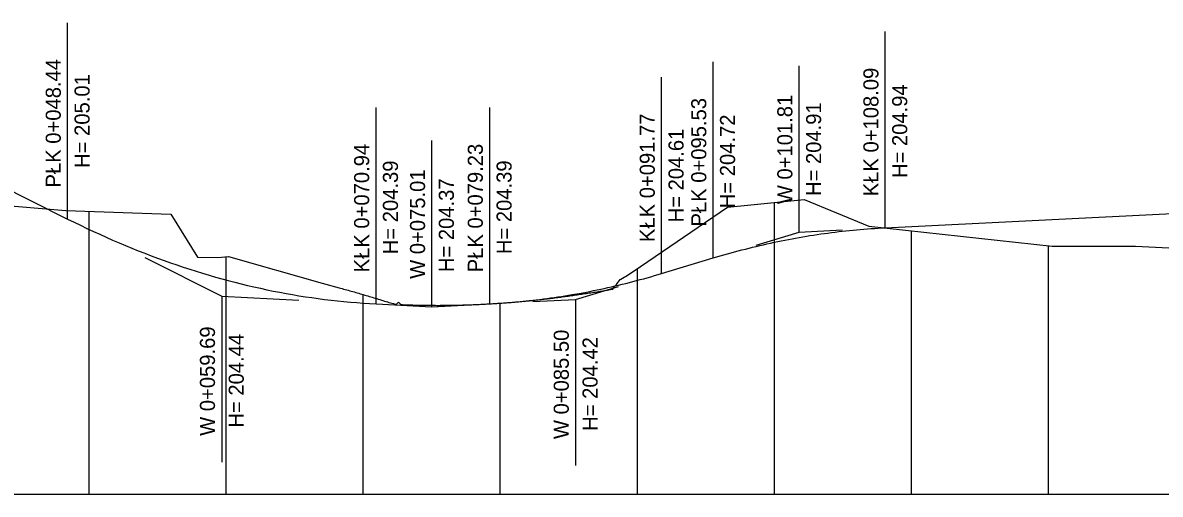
# Model space of a CAD drawing. Extents: x 6512707 to 6513007, y 6022307 to 6022469.
# Drawn here: x 6512789.6 to 6512872.6, y 6022368.6 to 6022402.9 of the extents above; entities that cross this region are included whole.
import ezdxf

# ---------------------------------------------------------------- set-up
doc = ezdxf.new("R2010")
doc.units = 0
doc.layers.add('1', color=7, linetype='Continuous')
doc.layers.add('42', color=7, linetype='Continuous')

msp = doc.modelspace()

# ---------------------------------------------------------------- linework, layer by layer
for p, q in [((6512772.058, 6022399.019), (6512792.862, 6022388.618)), ((6512772.058, 6022399.019), (6512792.862, 6022388.618)), ((6512852.505, 6022387.983), (6512903.729, 6022390.547)), ((6512852.505, 6022387.983), (6512903.729, 6022390.547)), ((6512836.189, 6022384.646), (6512839.946, 6022385.777)), ((6512836.189, 6022384.646), (6512839.946, 6022385.777)), ((6512815.356, 6022382.432), (6512819.433, 6022382.228)), ((6512815.356, 6022382.432), (6512819.433, 6022382.228)), ((6512819.433, 6022382.228), (6512823.647, 6022382.441)), ((6512819.433, 6022382.228), (6512823.647, 6022382.441))]:
    msp.add_line(p, q)
for points in [[(6512792.862, 6022388.618), (6512793.331, 6022388.386), (6512793.799, 6022388.158), (6512794.268, 6022387.935), (6512794.737, 6022387.716), (6512795.205, 6022387.502), (6512795.674, 6022387.291), (6512796.142, 6022387.086), (6512796.611, 6022386.884), (6512797.08, 6022386.687), (6512797.548, 6022386.495), (6512798.017, 6022386.307), (6512798.486, 6022386.123), (6512798.954, 6022385.943), (6512799.423, 6022385.769), (6512799.891, 6022385.598), (6512800.36, 6022385.432), (6512800.829, 6022385.27), (6512801.297, 6022385.112), (6512801.766, 6022384.959), (6512802.235, 6022384.811), (6512802.703, 6022384.667), (6512803.172, 6022384.527), (6512803.64, 6022384.391), (6512804.578, 6022384.134), (6512805.046, 6022384.011), (6512805.515, 6022383.893), (6512805.984, 6022383.78), (6512806.452, 6022383.671), (6512806.921, 6022383.566), (6512807.39, 6022383.466), (6512807.858, 6022383.37), (6512808.327, 6022383.278), (6512808.795, 6022383.191), (6512809.264, 6022383.108), (6512809.733, 6022383.03), (6512810.201, 6022382.956), (6512810.67, 6022382.886), (6512811.139, 6022382.821), (6512811.607, 6022382.76), (6512812.076, 6022382.704), (6512812.544, 6022382.652), (6512813.013, 6022382.604), (6512813.482, 6022382.561), (6512813.95, 6022382.522), (6512814.419, 6022382.488), (6512814.888, 6022382.458), (6512815.356, 6022382.432)], [(6512792.862, 6022388.618), (6512793.331, 6022388.386), (6512793.799, 6022388.158), (6512794.268, 6022387.935), (6512794.737, 6022387.716), (6512795.205, 6022387.502), (6512795.674, 6022387.291), (6512796.142, 6022387.086), (6512796.611, 6022386.884), (6512797.08, 6022386.687), (6512797.548, 6022386.495), (6512798.017, 6022386.307), (6512798.486, 6022386.123), (6512798.954, 6022385.943), (6512799.423, 6022385.769), (6512799.891, 6022385.598), (6512800.36, 6022385.432), (6512800.829, 6022385.27), (6512801.297, 6022385.112), (6512801.766, 6022384.959), (6512802.235, 6022384.811), (6512802.703, 6022384.667), (6512803.172, 6022384.527), (6512803.64, 6022384.391), (6512804.578, 6022384.134), (6512805.046, 6022384.011), (6512805.515, 6022383.893), (6512805.984, 6022383.78), (6512806.452, 6022383.671), (6512806.921, 6022383.566), (6512807.39, 6022383.466), (6512807.858, 6022383.37), (6512808.327, 6022383.278), (6512808.795, 6022383.191), (6512809.264, 6022383.108), (6512809.733, 6022383.03), (6512810.201, 6022382.956), (6512810.67, 6022382.886), (6512811.139, 6022382.821), (6512811.607, 6022382.76), (6512812.076, 6022382.704), (6512812.544, 6022382.652), (6512813.013, 6022382.604), (6512813.482, 6022382.561), (6512813.95, 6022382.522), (6512814.419, 6022382.488), (6512814.888, 6022382.458), (6512815.356, 6022382.432)], [(6512839.946, 6022385.777), (6512840.207, 6022385.855), (6512840.469, 6022385.932), (6512840.731, 6022386.008), (6512840.992, 6022386.082), (6512841.254, 6022386.154), (6512841.516, 6022386.225), (6512841.777, 6022386.295), (6512842.039, 6022386.364), (6512842.301, 6022386.431), (6512842.562, 6022386.497), (6512842.824, 6022386.561), (6512843.086, 6022386.624), (6512843.347, 6022386.686), (6512843.609, 6022386.746), (6512843.871, 6022386.805), (6512844.132, 6022386.863), (6512844.394, 6022386.919), (6512844.656, 6022386.974), (6512844.917, 6022387.028), (6512845.179, 6022387.08), (6512845.44, 6022387.13), (6512845.702, 6022387.18), (6512845.964, 6022387.228), (6512846.487, 6022387.32), (6512846.749, 6022387.364), (6512847.01, 6022387.406), (6512847.272, 6022387.447), (6512847.534, 6022387.487), (6512847.795, 6022387.526), (6512848.057, 6022387.563), (6512848.319, 6022387.598), (6512848.58, 6022387.633), (6512848.842, 6022387.666), (6512849.104, 6022387.697), (6512849.365, 6022387.727), (6512849.627, 6022387.756), (6512849.889, 6022387.784), (6512850.15, 6022387.81), (6512850.412, 6022387.835), (6512850.673, 6022387.858), (6512850.935, 6022387.88), (6512851.197, 6022387.901), (6512851.458, 6022387.92), (6512851.72, 6022387.938), (6512851.982, 6022387.954), (6512852.243, 6022387.969), (6512852.505, 6022387.983)], [(6512839.946, 6022385.777), (6512840.207, 6022385.855), (6512840.469, 6022385.932), (6512840.731, 6022386.008), (6512840.992, 6022386.082), (6512841.254, 6022386.154), (6512841.516, 6022386.225), (6512841.777, 6022386.295), (6512842.039, 6022386.364), (6512842.301, 6022386.431), (6512842.562, 6022386.497), (6512842.824, 6022386.561), (6512843.086, 6022386.624), (6512843.347, 6022386.686), (6512843.609, 6022386.746), (6512843.871, 6022386.805), (6512844.132, 6022386.863), (6512844.394, 6022386.919), (6512844.656, 6022386.974), (6512844.917, 6022387.028), (6512845.179, 6022387.08), (6512845.44, 6022387.13), (6512845.702, 6022387.18), (6512845.964, 6022387.228), (6512846.487, 6022387.32), (6512846.749, 6022387.364), (6512847.01, 6022387.406), (6512847.272, 6022387.447), (6512847.534, 6022387.487), (6512847.795, 6022387.526), (6512848.057, 6022387.563), (6512848.319, 6022387.598), (6512848.58, 6022387.633), (6512848.842, 6022387.666), (6512849.104, 6022387.697), (6512849.365, 6022387.727), (6512849.627, 6022387.756), (6512849.889, 6022387.784), (6512850.15, 6022387.81), (6512850.412, 6022387.835), (6512850.673, 6022387.858), (6512850.935, 6022387.88), (6512851.197, 6022387.901), (6512851.458, 6022387.92), (6512851.72, 6022387.938), (6512851.982, 6022387.954), (6512852.243, 6022387.969), (6512852.505, 6022387.983)], [(6512823.647, 6022382.441), (6512823.908, 6022382.454), (6512824.169, 6022382.47), (6512824.431, 6022382.486), (6512824.692, 6022382.504), (6512824.953, 6022382.523), (6512825.215, 6022382.544), (6512825.476, 6022382.566), (6512825.737, 6022382.59), (6512825.998, 6022382.614), (6512826.26, 6022382.64), (6512826.521, 6022382.668), (6512826.782, 6022382.697), (6512827.044, 6022382.727), (6512827.305, 6022382.759), (6512827.566, 6022382.792), (6512827.827, 6022382.826), (6512828.089, 6022382.862), (6512828.35, 6022382.899), (6512828.611, 6022382.937), (6512828.873, 6022382.977), (6512829.134, 6022383.018), (6512829.395, 6022383.061), (6512829.657, 6022383.105), (6512830.179, 6022383.196), (6512830.44, 6022383.244), (6512830.702, 6022383.294), (6512830.963, 6022383.344), (6512831.224, 6022383.397), (6512831.486, 6022383.45), (6512831.747, 6022383.505), (6512832.008, 6022383.561), (6512832.269, 6022383.618), (6512832.531, 6022383.677), (6512832.792, 6022383.738), (6512833.053, 6022383.799), (6512833.315, 6022383.862), (6512833.576, 6022383.927), (6512833.837, 6022383.992), (6512834.098, 6022384.06), (6512834.36, 6022384.128), (6512834.621, 6022384.198), (6512834.882, 6022384.269), (6512835.144, 6022384.342), (6512835.405, 6022384.416), (6512835.666, 6022384.491), (6512835.927, 6022384.567), (6512836.189, 6022384.646)], [(6512823.647, 6022382.441), (6512823.908, 6022382.454), (6512824.169, 6022382.47), (6512824.431, 6022382.486), (6512824.692, 6022382.504), (6512824.953, 6022382.523), (6512825.215, 6022382.544), (6512825.476, 6022382.566), (6512825.737, 6022382.59), (6512825.998, 6022382.614), (6512826.26, 6022382.64), (6512826.521, 6022382.668), (6512826.782, 6022382.697), (6512827.044, 6022382.727), (6512827.305, 6022382.759), (6512827.566, 6022382.792), (6512827.827, 6022382.826), (6512828.089, 6022382.862), (6512828.35, 6022382.899), (6512828.611, 6022382.937), (6512828.873, 6022382.977), (6512829.134, 6022383.018), (6512829.395, 6022383.061), (6512829.657, 6022383.105), (6512830.179, 6022383.196), (6512830.44, 6022383.244), (6512830.702, 6022383.294), (6512830.963, 6022383.344), (6512831.224, 6022383.397), (6512831.486, 6022383.45), (6512831.747, 6022383.505), (6512832.008, 6022383.561), (6512832.269, 6022383.618), (6512832.531, 6022383.677), (6512832.792, 6022383.738), (6512833.053, 6022383.799), (6512833.315, 6022383.862), (6512833.576, 6022383.927), (6512833.837, 6022383.992), (6512834.098, 6022384.06), (6512834.36, 6022384.128), (6512834.621, 6022384.198), (6512834.882, 6022384.269), (6512835.144, 6022384.342), (6512835.405, 6022384.416), (6512835.666, 6022384.491), (6512835.927, 6022384.567), (6512836.189, 6022384.646)]]:
    msp.add_lwpolyline(points)
at = {"layer": '1'}
for p, q in [((6512844.419, 6022368.562), (6512844.419, 6022389.818)), ((6512794.419, 6022368.562), (6512794.419, 6022389.178)), ((6512846.225, 6022387.669), (6512849.365, 6022387.826)), ((6512854.419, 6022368.562), (6512854.419, 6022387.76)), ((6512843.086, 6022386.723), (6512846.225, 6022387.669)), ((6512864.419, 6022368.562), (6512864.419, 6022386.656)), ((6512798.486, 6022385.807), (6512804.109, 6022382.995)), ((6512804.419, 6022368.562), (6512804.419, 6022385.871)), ((6512834.419, 6022368.562), (6512834.419, 6022385.005)), ((6512829.918, 6022382.757), (6512833.053, 6022383.701)), ((6512804.109, 6022382.995), (6512809.733, 6022382.714)), ((6512814.419, 6022368.562), (6512814.419, 6022383.111)), ((6512826.782, 6022382.599), (6512829.918, 6022382.757)), ((6512824.419, 6022368.562), (6512824.419, 6022382.489)), ((6512844.419, 6022368.562), (6512844.419, 6022370.562)), ((6512794.419, 6022368.562), (6512794.419, 6022369.562)), ((6512804.419, 6022368.562), (6512804.419, 6022369.562)), ((6512814.419, 6022368.562), (6512814.419, 6022369.562)), ((6512824.419, 6022368.562), (6512824.419, 6022369.562)), ((6512834.419, 6022368.562), (6512834.419, 6022369.562)), ((6512854.419, 6022368.562), (6512854.419, 6022369.562)), ((6512864.419, 6022368.562), (6512864.419, 6022369.562)), ((6512744.419, 6022368.562), (6512954.419, 6022368.562))]:
    msp.add_line(p, q, dxfattribs=at)
msp.add_lwpolyline([(6512785.792, 6022389.821), (6512792.74, 6022389.234), (6512800.397, 6022388.979), (6512802.33, 6022385.835), (6512803.827, 6022385.822), (6512804.601, 6022385.885), (6512811.417, 6022383.941), (6512812.664, 6022383.606), (6512812.774, 6022383.577), (6512812.884, 6022383.547), (6512812.994, 6022383.517), (6512813.104, 6022383.487), (6512813.214, 6022383.456), (6512813.324, 6022383.426), (6512813.434, 6022383.395), (6512813.544, 6022383.364), (6512813.654, 6022383.333), (6512813.764, 6022383.302), (6512813.874, 6022383.27), (6512813.984, 6022383.239), (6512814.094, 6022383.207), (6512814.204, 6022383.175), (6512814.314, 6022383.143), (6512814.423, 6022383.111), (6512814.533, 6022383.078), (6512814.643, 6022383.046), (6512814.753, 6022383.013), (6512814.863, 6022382.98), (6512814.973, 6022382.947), (6512815.083, 6022382.913), (6512815.193, 6022382.88), (6512815.303, 6022382.846), (6512815.413, 6022382.813), (6512815.523, 6022382.779), (6512815.633, 6022382.745), (6512815.743, 6022382.71), (6512815.853, 6022382.676), (6512815.963, 6022382.642), (6512816.073, 6022382.607), (6512816.089, 6022382.602), (6512816.183, 6022382.575), (6512816.293, 6022382.544), (6512816.402, 6022382.512), (6512816.512, 6022382.481), (6512816.622, 6022382.449), (6512816.732, 6022382.418), (6512816.764, 6022382.409), (6512816.842, 6022382.401), (6512816.857, 6022382.4), (6512816.952, 6022382.508), (6512816.997, 6022382.559), (6512817.062, 6022382.486), (6512817.154, 6022382.384), (6512817.172, 6022382.383), (6512817.282, 6022382.378), (6512817.392, 6022382.374), (6512817.502, 6022382.37), (6512817.612, 6022382.366), (6512817.722, 6022382.362), (6512817.832, 6022382.359), (6512817.942, 6022382.356), (6512818.052, 6022382.353), (6512818.162, 6022382.35), (6512818.272, 6022382.347), (6512818.381, 6022382.344), (6512818.491, 6022382.342), (6512818.601, 6022382.34), (6512818.711, 6022382.338), (6512818.821, 6022382.336), (6512818.931, 6022382.334), (6512819.041, 6022382.333), (6512819.151, 6022382.331), (6512819.261, 6022382.33), (6512819.371, 6022382.329), (6512819.481, 6022382.329), (6512819.591, 6022382.328), (6512819.701, 6022382.328), (6512819.811, 6022382.327), (6512819.921, 6022382.327), (6512820.031, 6022382.328), (6512820.141, 6022382.328), (6512820.25, 6022382.329), (6512820.36, 6022382.329), (6512820.47, 6022382.33), (6512820.58, 6022382.331), (6512820.69, 6022382.333), (6512820.8, 6022382.334), (6512820.91, 6022382.336), (6512821.02, 6022382.338), (6512821.13, 6022382.34), (6512821.24, 6022382.342), (6512821.35, 6022382.345), (6512821.46, 6022382.347), (6512821.57, 6022382.35), (6512821.68, 6022382.353), (6512821.79, 6022382.356), (6512821.9, 6022382.36), (6512822.01, 6022382.363), (6512822.12, 6022382.367), (6512822.229, 6022382.371), (6512822.339, 6022382.375), (6512822.449, 6022382.379), (6512822.559, 6022382.384), (6512822.669, 6022382.388), (6512822.779, 6022382.393), (6512822.889, 6022382.398), (6512822.999, 6022382.403), (6512823.109, 6022382.409), (6512823.219, 6022382.414), (6512823.329, 6022382.42), (6512823.439, 6022382.426), (6512823.549, 6022382.432), (6512823.659, 6022382.438), (6512823.769, 6022382.445), (6512823.879, 6022382.451), (6512823.989, 6022382.458), (6512824.099, 6022382.465), (6512824.208, 6022382.473), (6512824.318, 6022382.48), (6512824.428, 6022382.487), (6512824.538, 6022382.495), (6512824.648, 6022382.503), (6512824.758, 6022382.511), (6512824.868, 6022382.519), (6512824.978, 6022382.528), (6512825.088, 6022382.536), (6512825.198, 6022382.545), (6512825.308, 6022382.554), (6512825.418, 6022382.563), (6512825.528, 6022382.573), (6512825.638, 6022382.582), (6512825.748, 6022382.592), (6512825.858, 6022382.602), (6512825.968, 6022382.612), (6512826.078, 6022382.622), (6512826.187, 6022382.632), (6512826.297, 6022382.643), (6512826.407, 6022382.653), (6512826.517, 6022382.664), (6512826.627, 6022382.675), (6512826.737, 6022382.686), (6512826.847, 6022382.698), (6512826.957, 6022382.709), (6512827.067, 6022382.721), (6512827.177, 6022382.733), (6512827.287, 6022382.745), (6512827.397, 6022382.757), (6512827.507, 6022382.769), (6512827.617, 6022382.782), (6512827.727, 6022382.794), (6512827.837, 6022382.807), (6512827.947, 6022382.82), (6512828.057, 6022382.833), (6512828.166, 6022382.847), (6512828.276, 6022382.86), (6512828.386, 6022382.874), (6512828.496, 6022382.887), (6512828.606, 6022382.901), (6512828.716, 6022382.915), (6512828.826, 6022382.93), (6512828.936, 6022382.944), (6512829.046, 6022382.959), (6512829.156, 6022382.973), (6512829.266, 6022382.988), (6512829.376, 6022383.003), (6512829.486, 6022383.018), (6512829.596, 6022383.034), (6512829.706, 6022383.049), (6512829.816, 6022383.065), (6512829.926, 6022383.081), (6512830.036, 6022383.096), (6512830.145, 6022383.112), (6512830.255, 6022383.129), (6512830.365, 6022383.145), (6512830.475, 6022383.161), (6512830.585, 6022383.178), (6512830.695, 6022383.195), (6512830.805, 6022383.212), (6512830.915, 6022383.229), (6512831.025, 6022383.246), (6512831.135, 6022383.263), (6512831.245, 6022383.281), (6512831.355, 6022383.298), (6512831.465, 6022383.316), (6512831.575, 6022383.334), (6512831.685, 6022383.352), (6512831.795, 6022383.37), (6512831.905, 6022383.388), (6512832.015, 6022383.406), (6512832.124, 6022383.425), (6512832.234, 6022383.444), (6512832.344, 6022383.462), (6512832.454, 6022383.481), (6512832.564, 6022383.5), (6512832.619, 6022383.51), (6512832.674, 6022383.578), (6512832.784, 6022383.715), (6512832.894, 6022383.854), (6512833.004, 6022383.995), (6512833.114, 6022384.137), (6512833.174, 6022384.215), (6512833.224, 6022384.243), (6512833.334, 6022384.306), (6512833.444, 6022384.371), (6512833.554, 6022384.437), (6512833.664, 6022384.505), (6512833.774, 6022384.574), (6512833.884, 6022384.645), (6512833.994, 6022384.717), (6512834.104, 6022384.791), (6512841.002, 6022389.472), (6512846.593, 6022390.038), (6512851.292, 6022388.105), (6512864.674, 6022386.628), (6512870.758, 6022386.649), (6512880.453, 6022386.148)], dxfattribs=at)
at = {"layer": '42'}
for p, q in [((6512792.862, 6022388.618), (6512792.862, 6022402.918)), ((6512852.505, 6022387.983), (6512852.505, 6022402.283)), ((6512839.946, 6022385.777), (6512839.946, 6022400.077)), ((6512846.225, 6022387.669), (6512846.225, 6022399.769)), ((6512772.058, 6022399.019), (6512792.862, 6022388.618)), ((6512836.189, 6022384.646), (6512836.189, 6022398.946)), ((6512815.356, 6022382.432), (6512815.356, 6022396.732)), ((6512823.647, 6022382.441), (6512823.647, 6022396.741)), ((6512819.433, 6022382.228), (6512819.433, 6022394.328)), ((6512852.505, 6022387.983), (6512903.729, 6022390.547)), ((6512836.189, 6022384.646), (6512839.946, 6022385.777)), ((6512804.109, 6022382.995), (6512804.109, 6022370.895)), ((6512829.918, 6022382.757), (6512829.918, 6022370.657)), ((6512815.356, 6022382.432), (6512819.433, 6022382.228)), ((6512819.433, 6022382.228), (6512823.647, 6022382.441))]:
    msp.add_line(p, q, dxfattribs=at)
for points in [[(6512792.862, 6022388.618), (6512793.331, 6022388.386), (6512793.799, 6022388.158), (6512794.268, 6022387.935), (6512794.737, 6022387.716), (6512795.205, 6022387.502), (6512795.674, 6022387.291), (6512796.142, 6022387.086), (6512796.611, 6022386.884), (6512797.08, 6022386.687), (6512797.548, 6022386.495), (6512798.017, 6022386.307), (6512798.486, 6022386.123), (6512798.954, 6022385.943), (6512799.423, 6022385.769), (6512799.891, 6022385.598), (6512800.36, 6022385.432), (6512800.829, 6022385.27), (6512801.297, 6022385.112), (6512801.766, 6022384.959), (6512802.235, 6022384.811), (6512802.703, 6022384.667), (6512803.172, 6022384.527), (6512803.64, 6022384.391), (6512804.578, 6022384.134), (6512805.046, 6022384.011), (6512805.515, 6022383.893), (6512805.984, 6022383.78), (6512806.452, 6022383.671), (6512806.921, 6022383.566), (6512807.39, 6022383.466), (6512807.858, 6022383.37), (6512808.327, 6022383.278), (6512808.795, 6022383.191), (6512809.264, 6022383.108), (6512809.733, 6022383.03), (6512810.201, 6022382.956), (6512810.67, 6022382.886), (6512811.139, 6022382.821), (6512811.607, 6022382.76), (6512812.076, 6022382.704), (6512812.544, 6022382.652), (6512813.013, 6022382.604), (6512813.482, 6022382.561), (6512813.95, 6022382.522), (6512814.419, 6022382.488), (6512814.888, 6022382.458), (6512815.356, 6022382.432)], [(6512839.946, 6022385.777), (6512840.207, 6022385.855), (6512840.469, 6022385.932), (6512840.731, 6022386.008), (6512840.992, 6022386.082), (6512841.254, 6022386.154), (6512841.516, 6022386.225), (6512841.777, 6022386.295), (6512842.039, 6022386.364), (6512842.301, 6022386.431), (6512842.562, 6022386.497), (6512842.824, 6022386.561), (6512843.086, 6022386.624), (6512843.347, 6022386.686), (6512843.609, 6022386.746), (6512843.871, 6022386.805), (6512844.132, 6022386.863), (6512844.394, 6022386.919), (6512844.656, 6022386.974), (6512844.917, 6022387.028), (6512845.179, 6022387.08), (6512845.44, 6022387.13), (6512845.702, 6022387.18), (6512845.964, 6022387.228), (6512846.487, 6022387.32), (6512846.749, 6022387.364), (6512847.01, 6022387.406), (6512847.272, 6022387.447), (6512847.534, 6022387.487), (6512847.795, 6022387.526), (6512848.057, 6022387.563), (6512848.319, 6022387.598), (6512848.58, 6022387.633), (6512848.842, 6022387.666), (6512849.104, 6022387.697), (6512849.365, 6022387.727), (6512849.627, 6022387.756), (6512849.889, 6022387.784), (6512850.15, 6022387.81), (6512850.412, 6022387.835), (6512850.673, 6022387.858), (6512850.935, 6022387.88), (6512851.197, 6022387.901), (6512851.458, 6022387.92), (6512851.72, 6022387.938), (6512851.982, 6022387.954), (6512852.243, 6022387.969), (6512852.505, 6022387.983)], [(6512823.647, 6022382.441), (6512823.908, 6022382.454), (6512824.169, 6022382.47), (6512824.431, 6022382.486), (6512824.692, 6022382.504), (6512824.953, 6022382.523), (6512825.215, 6022382.544), (6512825.476, 6022382.566), (6512825.737, 6022382.59), (6512825.998, 6022382.614), (6512826.26, 6022382.64), (6512826.521, 6022382.668), (6512826.782, 6022382.697), (6512827.044, 6022382.727), (6512827.305, 6022382.759), (6512827.566, 6022382.792), (6512827.827, 6022382.826), (6512828.089, 6022382.862), (6512828.35, 6022382.899), (6512828.611, 6022382.937), (6512828.873, 6022382.977), (6512829.134, 6022383.018), (6512829.395, 6022383.061), (6512829.657, 6022383.105), (6512830.179, 6022383.196), (6512830.44, 6022383.244), (6512830.702, 6022383.294), (6512830.963, 6022383.344), (6512831.224, 6022383.397), (6512831.486, 6022383.45), (6512831.747, 6022383.505), (6512832.008, 6022383.561), (6512832.269, 6022383.618), (6512832.531, 6022383.677), (6512832.792, 6022383.738), (6512833.053, 6022383.799), (6512833.315, 6022383.862), (6512833.576, 6022383.927), (6512833.837, 6022383.992), (6512834.098, 6022384.06), (6512834.36, 6022384.128), (6512834.621, 6022384.198), (6512834.882, 6022384.269), (6512835.144, 6022384.342), (6512835.405, 6022384.416), (6512835.666, 6022384.491), (6512835.927, 6022384.567), (6512836.189, 6022384.646)]]:
    msp.add_lwpolyline(points, dxfattribs=at)

# ---------------------------------------------------------------- texts
for s, p in [('PŁK 0+048.44', (6512792.362, 6022390.914)), ('KŁK 0+108.09', (6512852.005, 6022390.276)), ('H= 205.01', (6512794.462, 6022392.343)), ('H= 204.94', (6512854.105, 6022391.604)), ('PŁK 0+095.53', (6512839.446, 6022388.071)), ('W 0+101.81', (6512845.725, 6022389.697)), ('H= 204.91', (6512847.825, 6022390.294)), ('KŁK 0+091.77', (6512835.689, 6022386.939)), ('H= 204.72', (6512841.546, 6022389.402)), ('H= 204.61', (6512837.789, 6022388.371)), ('KŁK 0+070.94', (6512814.856, 6022384.729)), ('PŁK 0+079.23', (6512823.147, 6022384.734)), ('H= 204.39', (6512816.956, 6022386.05)), ('H= 204.39', (6512825.247, 6022386.058)), ('W 0+075.01', (6512818.933, 6022384.256)), ('H= 204.37', (6512821.033, 6022384.747)), ('W 0+059.69', (6512803.609, 6022372.816)), ('W 0+085.50', (6512829.418, 6022372.58)), ('H= 204.44', (6512805.709, 6022373.416)), ('H= 204.42', (6512831.518, 6022373.181))]:
    msp.add_text(s, height=1.1, rotation=90, dxfattribs=at).set_placement(p)

doc.saveas('drawing.dxf')
